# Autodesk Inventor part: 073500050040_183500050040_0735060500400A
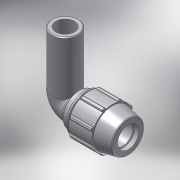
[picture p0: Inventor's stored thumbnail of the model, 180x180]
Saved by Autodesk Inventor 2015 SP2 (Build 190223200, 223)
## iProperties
Created: 2017-02
Part Number: 073500050040_183500050040_0735060500400A
Material: PVC-Piping
Description: PLASSON 90° ELBOW ADAPTOR 50-40
Document SubType Name: Modeling
Designer: KIM
Mass: 92.6774 g
Surface Area: 199.44 cm^2
Volume: 66.1981 cm^3
Density: 1.4 g/cm^3
Appearance: Smooth - White
Author: KIM
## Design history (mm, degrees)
derived "07350.ipt"
feature "Solid1::07350.ipt"
tag "TaggingFeature1"
body "Solid1"
other parameters: "d4" = 11.33333, "d5" = 34, "d7" = 96, "d11" = 4.53333, "d13" = 120 deg, "d15" = 12 deg, "d16" = 83.52, "d18" = 2.5, "d19" = 35 deg, "d20" = 17.5 deg, "d21" = 89.28, "d23" = 0, "d25" = 360 deg, "d27" = 1.92, "d33" = 1, "d42" = 50.32, "d43" = 2.88, "d46" = 1.5, "d51" = 136, "d68" = 4.53333, "d72" = 106, "d76" = 28, "d79" = 16, "d80" = 1.2, "d91" = 72, "d93" = 93, "d95" = 28, "d96" = 11.33333, "d97" = 50 deg, "d98" = 63.6, "d99" = 0, "d100" = 0, "E_" = 96, "A_" = 136, "l_" = 93, "A_1" = 106
